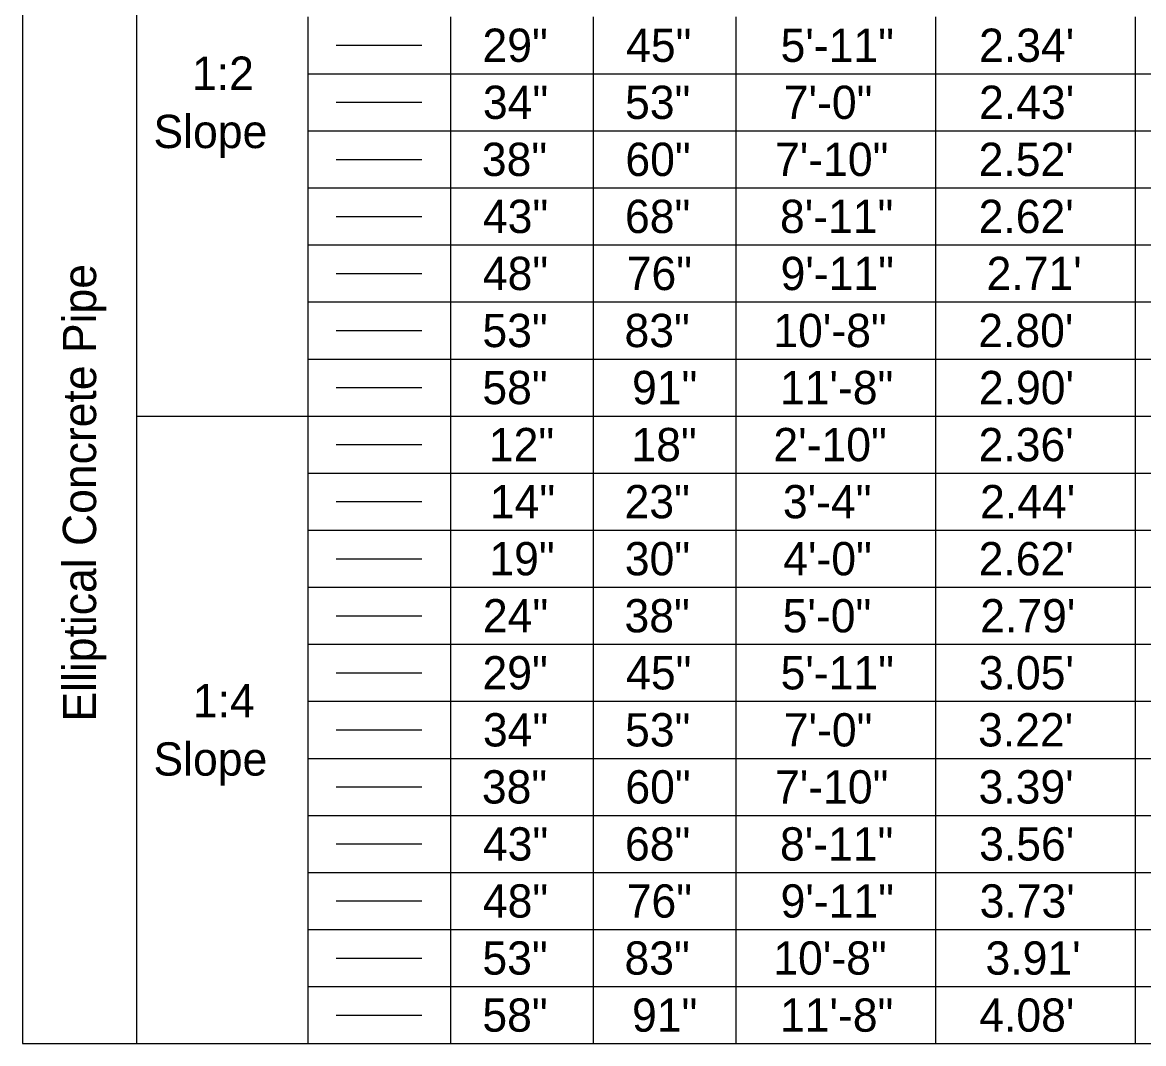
# Model space of a CAD drawing. Extents: x -1.3 to 14.6, y 0 to 8.4.
# Drawn here: x 1.7 to 4.058, y 2.19 to 4.338 of the extents above; entities that cross this region are included whole.
import ezdxf

# ---------------------------------------------------------------- set-up
doc = ezdxf.new("R2010")
doc.units = 0
doc.layers.add('Table', color=7, linetype='Continuous')

msp = doc.modelspace()

# ---------------------------------------------------------------- linework, layer by layer
at = {"layer": 'Table'}
for p, q in [((2.36, 4.29), (2.54, 4.29)), ((2.36, 4.17), (2.54, 4.17)), ((2.36, 4.05), (2.54, 4.05)), ((2.36, 3.93), (2.54, 3.93)), ((2.36, 3.81), (2.54, 3.81)), ((2.36, 3.69), (2.54, 3.69)), ((2.36, 3.57), (2.54, 3.57)), ((2.36, 3.45), (2.54, 3.45)), ((2.36, 3.33), (2.54, 3.33)), ((2.36, 3.21), (2.54, 3.21)), ((2.36, 3.09), (2.54, 3.09)), ((2.36, 2.97), (2.54, 2.97)), ((2.36, 2.85), (2.54, 2.85)), ((2.36, 2.73), (2.54, 2.73)), ((2.36, 2.61), (2.54, 2.61)), ((2.36, 2.49), (2.54, 2.49)), ((2.36, 2.37), (2.54, 2.37)), ((2.36, 2.25), (2.54, 2.25))]:
    msp.add_line(p, q, dxfattribs=at)
for points in [[(1.94, 8.43), (1.94, 7.83), (1.94, 7.47), (1.94, 6.15), (1.94, 4.83), (1.94, 3.51), (1.94, 2.19)], [(1.7, 7.47), (1.7, 4.83), (1.7, 2.19)], [(2.3, 4.35), (2.3, 4.23), (2.3, 4.11), (2.3, 3.99), (2.3, 3.87), (2.3, 3.75), (2.3, 3.63), (2.3, 3.51), (2.3, 3.39), (2.3, 3.27), (2.3, 3.15), (2.3, 3.03), (2.3, 2.91), (2.3, 2.79), (2.3, 2.67), (2.3, 2.55), (2.3, 2.43), (2.3, 2.31), (2.3, 2.19)], [(2.6, 4.35), (2.6, 4.23), (2.6, 4.11), (2.6, 3.99), (2.6, 3.87), (2.6, 3.75), (2.6, 3.63), (2.6, 3.51), (2.6, 3.39), (2.6, 3.27), (2.6, 3.15), (2.6, 3.03), (2.6, 2.91), (2.6, 2.79), (2.6, 2.67), (2.6, 2.55), (2.6, 2.43), (2.6, 2.31), (2.6, 2.19)], [(2.9, 4.35), (2.9, 4.23), (2.9, 4.11), (2.9, 3.99), (2.9, 3.87), (2.9, 3.75), (2.9, 3.63), (2.9, 3.51), (2.9, 3.39), (2.9, 3.27), (2.9, 3.15), (2.9, 3.03), (2.9, 2.91), (2.9, 2.79), (2.9, 2.67), (2.9, 2.55), (2.9, 2.43), (2.9, 2.31), (2.9, 2.19)], [(3.2, 4.35), (3.2, 4.23), (3.2, 4.11), (3.2, 3.99), (3.2, 3.87), (3.2, 3.75), (3.2, 3.63), (3.2, 3.51), (3.2, 3.39), (3.2, 3.27), (3.2, 3.15), (3.2, 3.03), (3.2, 2.91), (3.2, 2.79), (3.2, 2.67), (3.2, 2.55), (3.2, 2.43), (3.2, 2.31), (3.2, 2.19)], [(3.62, 4.35), (3.62, 4.23), (3.62, 4.11), (3.62, 3.99), (3.62, 3.87), (3.62, 3.75), (3.62, 3.63), (3.62, 3.51), (3.62, 3.39), (3.62, 3.27), (3.62, 3.15), (3.62, 3.03), (3.62, 2.91), (3.62, 2.79), (3.62, 2.67), (3.62, 2.55), (3.62, 2.43), (3.62, 2.31), (3.62, 2.19)], [(4.04, 4.35), (4.04, 4.23), (4.04, 4.11), (4.04, 3.99), (4.04, 3.87), (4.04, 3.75), (4.04, 3.63), (4.04, 3.51), (4.04, 3.39), (4.04, 3.27), (4.04, 3.15), (4.04, 3.03), (4.04, 2.91), (4.04, 2.79), (4.04, 2.67), (4.04, 2.55), (4.04, 2.43), (4.04, 2.31), (4.04, 2.19)], [(2.3, 4.23), (2.6, 4.23), (2.9, 4.23), (3.2, 4.23), (3.62, 4.23), (4.04, 4.23), (4.52, 4.23)], [(2.3, 4.11), (2.6, 4.11), (2.9, 4.11), (3.2, 4.11), (3.62, 4.11), (4.04, 4.11), (4.52, 4.11)], [(2.3, 3.99), (2.6, 3.99), (2.9, 3.99), (3.2, 3.99), (3.62, 3.99), (4.04, 3.99), (4.52, 3.99)], [(2.3, 3.87), (2.6, 3.87), (2.9, 3.87), (3.2, 3.87), (3.62, 3.87), (4.04, 3.87), (4.52, 3.87)], [(2.3, 3.75), (2.6, 3.75), (2.9, 3.75), (3.2, 3.75), (3.62, 3.75), (4.04, 3.75), (4.52, 3.75)], [(2.3, 3.63), (2.6, 3.63), (2.9, 3.63), (3.2, 3.63), (3.62, 3.63), (4.04, 3.63), (4.52, 3.63)], [(1.94, 3.51), (2.3, 3.51), (2.6, 3.51), (2.9, 3.51), (3.2, 3.51), (3.62, 3.51), (4.04, 3.51), (4.52, 3.51)], [(2.3, 3.39), (2.6, 3.39), (2.9, 3.39), (3.2, 3.39), (3.62, 3.39), (4.04, 3.39), (4.52, 3.39)], [(2.3, 3.27), (2.6, 3.27), (2.9, 3.27), (3.2, 3.27), (3.62, 3.27), (4.04, 3.27), (4.52, 3.27)], [(2.3, 3.15), (2.6, 3.15), (2.9, 3.15), (3.2, 3.15), (3.62, 3.15), (4.04, 3.15), (4.52, 3.15)], [(2.3, 3.03), (2.6, 3.03), (2.9, 3.03), (3.2, 3.03), (3.62, 3.03), (4.04, 3.03), (4.52, 3.03)], [(2.3, 2.91), (2.6, 2.91), (2.9, 2.91), (3.2, 2.91), (3.62, 2.91), (4.04, 2.91), (4.52, 2.91)], [(2.3, 2.79), (2.6, 2.79), (2.9, 2.79), (3.2, 2.79), (3.62, 2.79), (4.04, 2.79), (4.52, 2.79)], [(2.3, 2.67), (2.6, 2.67), (2.9, 2.67), (3.2, 2.67), (3.62, 2.67), (4.04, 2.67), (4.52, 2.67)], [(2.3, 2.55), (2.6, 2.55), (2.9, 2.55), (3.2, 2.55), (3.62, 2.55), (4.04, 2.55), (4.52, 2.55)], [(2.3, 2.43), (2.6, 2.43), (2.9, 2.43), (3.2, 2.43), (3.62, 2.43), (4.04, 2.43), (4.52, 2.43)], [(2.3, 2.31), (2.6, 2.31), (2.9, 2.31), (3.2, 2.31), (3.62, 2.31), (4.04, 2.31), (4.52, 2.31)], [(1.7, 2.19), (1.94, 2.19), (2.3, 2.19), (2.6, 2.19), (2.9, 2.19), (3.2, 2.19), (3.62, 2.19), (4.04, 2.19), (4.52, 2.19)]]:
    msp.add_lwpolyline(points, dxfattribs=at)

# ---------------------------------------------------------------- texts
for s, rotation, p in [('29"', 0, (2.6675, 4.255)), ('45"', 0, (2.9695, 4.255)), ('5\'-11"', 0, (3.2944, 4.255)), ("2.34'", 0, (3.7118, 4.255)), ('34"', 0, (2.6684, 4.135)), ('53"', 0, (2.9673, 4.135)), ('7\'-0"', 0, (3.3011, 4.135)), ("2.43'", 0, (3.7118, 4.135)), ('38"', 0, (2.6661, 4.015)), ('60"', 0, (2.968, 4.015)), ('7\'-10"', 0, (3.2827, 4.015)), ("2.52'", 0, (3.7108, 4.015)), ('43"', 0, (2.6684, 3.895)), ('68"', 0, (2.9672, 3.895)), ('8\'-11"', 0, (3.2931, 3.895)), ("2.62'", 0, (3.7109, 3.895)), ('48"', 0, (2.6682, 3.775)), ('76"', 0, (2.9708, 3.775)), ('9\'-11"', 0, (3.2944, 3.775)), ("2.71'", 0, (3.7276, 3.775)), ('Elliptical Concrete Pipe', 90, (1.855, 2.8673)), ('53"', 0, (2.6673, 3.655)), ('83"', 0, (2.9661, 3.655)), ('10\'-8"', 0, (3.2791, 3.655)), ("2.80'", 0, (3.7101, 3.655)), ('58"', 0, (2.6672, 3.535)), ('91"', 0, (2.982, 3.535)), ('11\'-8"', 0, (3.2931, 3.535)), ("2.90'", 0, (3.7114, 3.535)), ('12"', 0, (2.6809, 3.415)), ('18"', 0, (2.9807, 3.415)), ('2\'-10"', 0, (3.2793, 3.415)), ("2.36'", 0, (3.7108, 3.415)), ('14"', 0, (2.683, 3.295)), ('23"', 0, (2.9663, 3.295)), ('3\'-4"', 0, (3.2992, 3.295)), ("2.44'", 0, (3.7139, 3.295)), ('19"', 0, (2.682, 3.175)), ('30"', 0, (2.9668, 3.175)), ('4\'-0"', 0, (3.2999, 3.175)), ("2.62'", 0, (3.7109, 3.175)), ('24"', 0, (2.6684, 3.055)), ('38"', 0, (2.9661, 3.055)), ('5\'-0"', 0, (3.2988, 3.055)), ("2.79'", 0, (3.7142, 3.055)), ('29"', 0, (2.6675, 2.935)), ('45"', 0, (2.9695, 2.935)), ('5\'-11"', 0, (3.2944, 2.935)), ("3.05'", 0, (3.7113, 2.935)), ('34"', 0, (2.6684, 2.815)), ('53"', 0, (2.9673, 2.815)), ('7\'-0"', 0, (3.3011, 2.815)), ("3.22'", 0, (3.7097, 2.815)), ('38"', 0, (2.6661, 2.695)), ('60"', 0, (2.968, 2.695)), ('7\'-10"', 0, (3.2827, 2.695)), ("3.39'", 0, (3.7107, 2.695)), ('43"', 0, (2.6684, 2.575)), ('68"', 0, (2.9672, 2.575)), ('8\'-11"', 0, (3.2931, 2.575)), ("3.56'", 0, (3.7119, 2.575)), ('48"', 0, (2.6682, 2.455)), ('76"', 0, (2.9708, 2.455)), ('9\'-11"', 0, (3.2944, 2.455)), ("3.73'", 0, (3.7129, 2.455)), ('53"', 0, (2.6673, 2.335)), ('83"', 0, (2.9661, 2.335)), ('10\'-8"', 0, (3.2791, 2.335)), ("3.91'", 0, (3.7253, 2.335)), ('58"', 0, (2.6672, 2.215)), ('91"', 0, (2.982, 2.215)), ('11\'-8"', 0, (3.2931, 2.215)), ("4.08'", 0, (3.7122, 2.215))]:
    msp.add_text(s, height=0.07, rotation=rotation, dxfattribs=at).set_placement(p)
for s, p in [('1:2', (2.0566, 4.1962)), ('Slope', (1.9756, 4.0737)), ('1:4', (2.0583, 2.8762)), ('Slope', (1.9756, 2.7537))]:
    msp.add_text(s, height=0.07, dxfattribs=at).set_placement(p)

doc.saveas('drawing.dxf')
